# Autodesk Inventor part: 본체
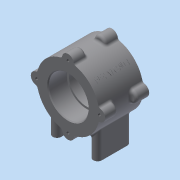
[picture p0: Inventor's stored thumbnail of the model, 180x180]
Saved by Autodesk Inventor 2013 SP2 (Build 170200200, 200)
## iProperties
Created: 2015-03
Part Number: 본체
Material: 일반
Document SubType Name: Modeling
Designer: dgall
Density: 1 g/cm^3
Author: dgall
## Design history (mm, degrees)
sketch "스케치1"
  geometry: C1 r 37 at (0, 0); C2 r 21 at (0, 0); C3 r 23.5 at (0, 0); 1 further point
  constraints: 3 centre point, 3 coincident
  dimensions: "d0" = 74 diameter of C1; "d3" = 42 diameter of C2; "d6" = 47 diameter of C3
extrude "돌출1" new body sketch "스케치1" distance "d1" = 52; taper "d2" = 0 deg
extrude "돌출2" cut sketch "스케치1" stored distance "d4" = 0; taper "d5" = 0 deg
extrude "돌출3" cut sketch "스케치1" distance "d7" = 22; taper "d8" = 0 deg
node "작업 평면1"
node "작업 평면2"
sketch "스케치2"
  geometry: L1 (19, -11)-(29, -11); L2 (29, -11)-(29, -41); L3 (29, -41)-(19, -41); L4 (19, -41)-(19, -11); L5 (37, 0)-(37, -52) reference; A1 r 5 centre (24, -11) between (29, -11) and (19, -11); A2 r 5 centre (24, -41) between (19, -41) and (29, -41); 3 further points
  constraints: 8 end point, 4 point on circle, 4 tangent, 2 centre point, 2 midpoint, 2 parallel, 1 horizontal, 1 horizontal alignment, 1 perpendicular
  dimensions: "d10" = 10 distance between parallel lines of L2 L4; "d12" = 40 dimension on A2 A1; "d13" = 24 horizontal distance of point (0, 0) A1.centre
extrude "돌출4" join sketch "스케치2" stored distance "d14" = 56; taper "d15" = 0 deg
fillet "모깎기1" dims "d16" = 3
sketch "스케치3"
  geometry: C1 r 23.5 at (0, 0) reference; C2 r 7 at (0, -37); 2 further points
  constraints: 2 vertical alignment, 1 centre point, 1 coincident, 1 other
  dimensions: "d19" = 7 radius of C2
extrude "돌출5" join sketch "스케치3" distance "d21" = 15; taper "d22" = 0 deg
hole "구멍1" sketch "스케치3" diameter "d23" = 3.242; stored, may be unused: countersink angle "d27" = 90 deg, drill point angle "d29" = 118 deg; dims "d24" = 8, "d25" = 4, "d26" = 2, "d28" = 11
fillet "모깎기2" dims "d30" = 3
fillet "모깎기3" dims "d31" = 3
node "작업 평면3"
sketch "스케치4"
  geometry: L1 (19, 11)-(19, 41) reference; L2 (29, 41)-(29, 11) reference; A1 r 5 centre (-24, 41) between (-19, 41) and (-29, 41) reference; A2 r 5 centre (-24, 11) between (-29, 11) and (-19, 11) reference; A3 r 5 centre (24, 11) between (19, 11) and (29, 11) reference; A4 r 5 centre (24, 41) between (29, 41) and (19, 41) reference; 5 further points
  constraints: 4 coincident
hole "구멍2" sketch "스케치4" at (24, 11), (24, 41), (-24, 11), (-24, 41) diameter "d35" = 4.134; stored, may be unused: countersink angle "d39" = 90 deg, drill point angle "d41" = 118 deg; dims "d36" = 3, "d37" = 4, "d38" = 2, "d40" = 8
fillet "모깎기4" dims "d42" = 0.3
chamfer "모따기1" distance "d43" = 1; stored, may be unused: second distance "d44" = 2, angle "d45" = 45 deg
sketch "스케치5"
  geometry: L1 (0, 0)-(44, 0); L2 (0, 0)-(26.163, -26.163); L3 (7.84, -36.16)-(44, 0); A1 r 37 centre (0, 0) between (9.104, -35.862) and (35.862, -9.104) reference; A2 r 7 centre (37, 0) between (38.239, -6.889) and (38.239, 6.889) reference
  constraints: 6 end point, 3 point on circle, 1 horizontal
  dimensions: "d46" = 45 deg angle of L1 L2; "d47" = 90 deg angle of L2 L3
node "작업 평면5"
  node "작업 평면4"
sketch "스케치6"
  geometry: L1 (-18.921, -52)-(18.921, -52) reference; 2 further points
  constraints: 1 vertical alignment, 1 other
  dimensions: "d49" = 26 distance from line of L1 point (0, -26)
feature "엠보싱1" sketch "스케치6" dims "d50" = 0.5, "d51" = 0
node "솔리드1"
mirror "대칭1"
mirror "대칭2"
pattern_circular "원형 패턴1" dims "d33" = 360 deg
mirror "대칭3"
node "투영된 루프1"
other parameters: "d9" = 56, "d48" = 90 deg
